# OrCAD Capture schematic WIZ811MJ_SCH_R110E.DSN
size B; title: WIZ811MJ; rev: 1.1; company: JaeHo Lee
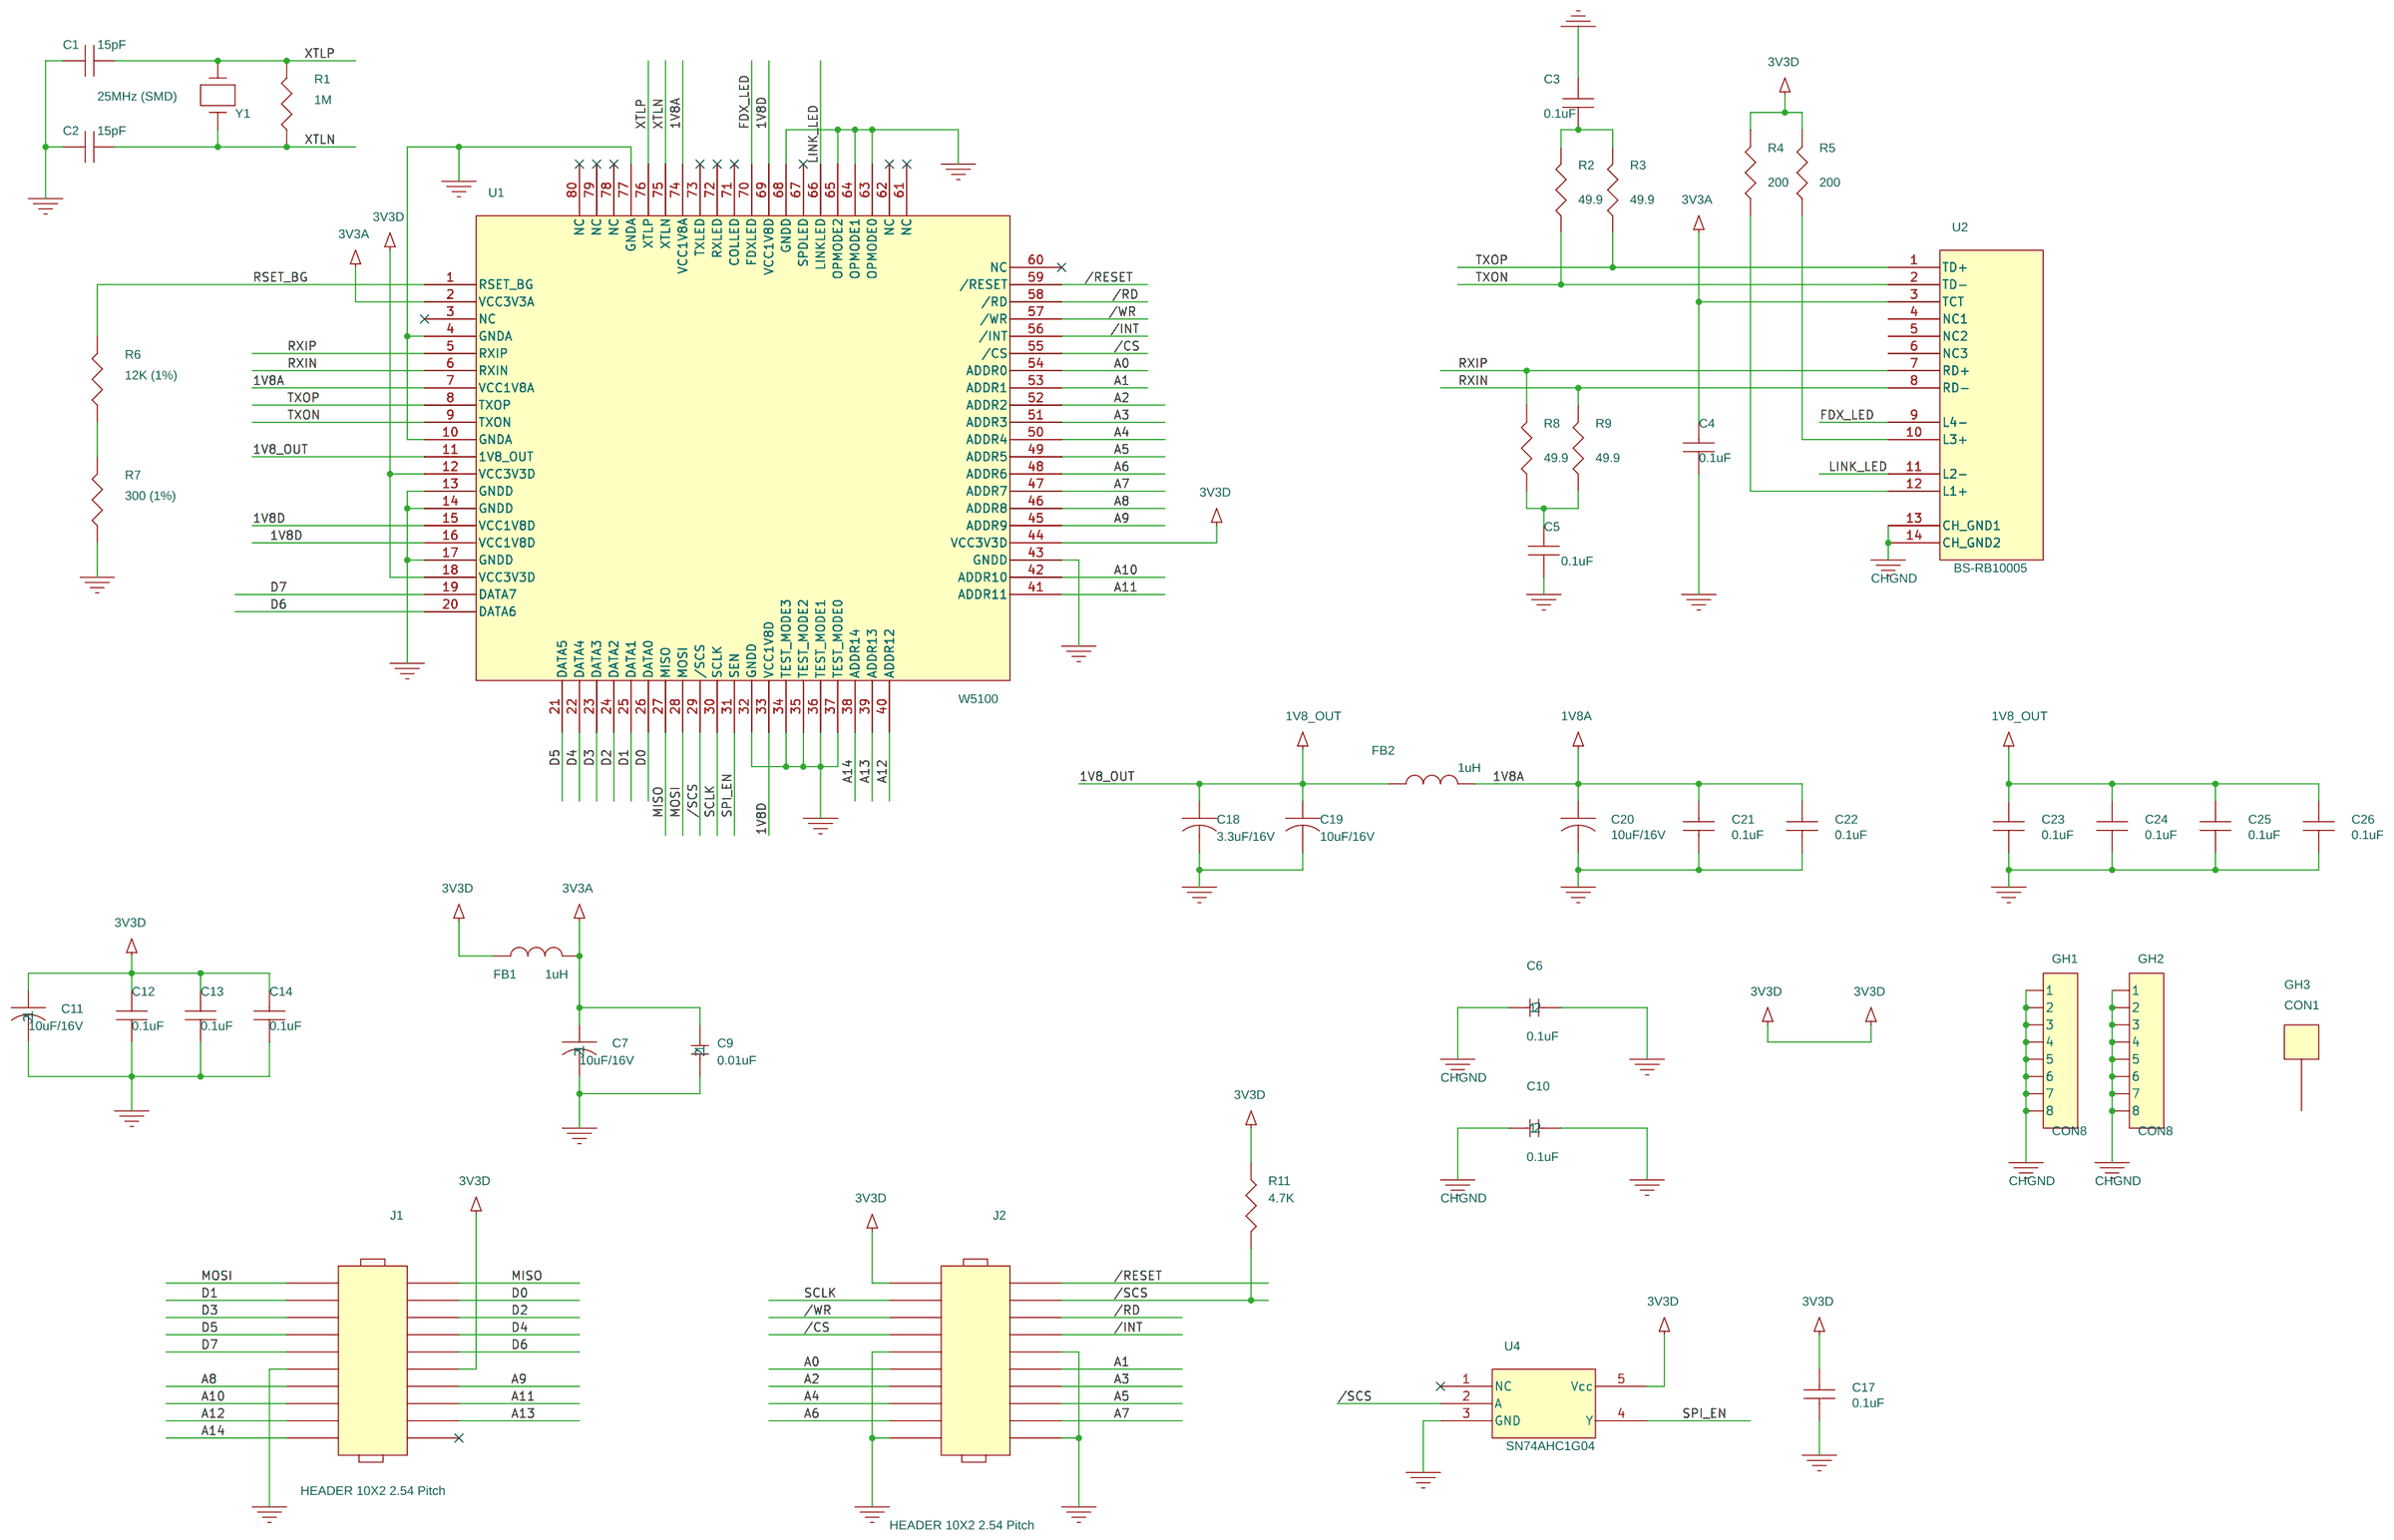
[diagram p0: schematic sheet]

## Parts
C1  15pF
C2  15pF
C3  0.1uF
C4  0.1uF
C5  0.1uF
C6  0.1uF  [C0603]
C7  10uF/16V  [CAP\B\3528]
C9  0.01uF  [C0603]
C10  0.1uF  [C0603]
C11  10uF/16V  [CAP\B\3528]
C12  0.1uF
C13  0.1uF
C14  0.1uF
C17  0.1uF
C18  3.3uF/16V
C19  10uF/16V
C20  10uF/16V
C21  0.1uF
C22  0.1uF
C23  0.1uF
C24  0.1uF
C25  0.1uF
C26  0.1uF
FB1  1uH  [L0805]
FB2  1uH  [L0805]
GH1  CON8
GH2  CON8
GH3  CON1
J1  HEADER 10X2 2.54 Pitch
J2  HEADER 10X2 2.54 Pitch
R1  1M
R2  49.9
R3  49.9
R4  200
R5  200
R6  12K (1%)
R7  300 (1%)
R8  49.9
R9  49.9
R11  4.7K
U1  W5100
U2  BS-RB10005
U4  SN74AHC1G04
Y1  25MHz (SMD)

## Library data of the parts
C1-C5 C12-C14 C17 C21-C26 = CAP_NP
C6 = CAP_0.01uF_0603
C7 = CAP_4.7uF_B
C9 = CAP_0.01uF_0603_2
C10 = CAP_0.01uF_0603_1
C11 = CAP_4.7uF_B_1
C18-C20 = C
FB1 FB2 = FB_0805
GH1 = CON8_1
GH2 = CON8
GH3 = CON1
J1 J2 = HEADER_10X2
R1-R9 R11 = R
U1 = W5100_7
U2 = RJ113BZ_0
U4 = SN74AHC1G04
Y1 = CRYSTAL

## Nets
1V8A: C20.1 C21.1 C22.1 FB2.2 U1.7(VCC1V8A) U1.74(VCC1V8A)
1V8D: C18.1 C19.1 C23.1 C24.1 C25.1 C26.1 FB2.1 U1.11(1V8_OUT) U1.15(VCC1V8D) U1.16(VCC1V8D) U1.33(VCC1V8D) U1.69(VCC1V8D)
3V3A: C4.1 C7.1 C9.1 FB1.2 U1.2(VCC3V3A) U2.3(TCT)
3V3D: C11.1 C12.1 C13.1 C14.1 C17.1 FB1.1 J1.12 J2.1 R4.2 R5.2 R11.1 U1.12(VCC3V3D) U1.18(VCC3V3D) U1.44(VCC3V3D) U4.5(Vcc)
GND: C1.2 C2.2 C3.1 C4.2 C5.2 C6.2 C7.2 C9.2 C10.2 C11.2 C12.2 C13.2 C14.2 C17.2 C18.2 C19.2 C20.2 C21.2 C22.2 C23.2 C24.2 C25.2 C26.2 J1.11 J2.9 J2.10 J2.19 J2.20 R7.1 U1.4(GNDA) U1.10(GNDA) U1.13(GNDD) U1.14(GNDD) U1.17(GNDD) U1.32(GNDD) U1.34(TEST_MODE3) U1.35(TEST_MODE2) U1.36(TEST_MODE1) U1.37(TEST_MODE0) U1.43(GNDD) U1.63(OPMODE0) U1.64(OPMODE1) U1.65(OPMODE2) U1.68(GNDD) U1.77(GNDA) U4.3(GND)
/CS: J2.7 U1.55(/CS)
/INT: J2.8 U1.56(/INT)
/RD: J2.6 U1.58(/RD)
/RESET: J2.2 U1.59(/RESET)
/SCS: J2.4 R11.2 U1.29(/SCS) U4.2(A)
/WR: J2.5 U1.57(/WR)
A0: J2.11 U1.54(ADDR0)
A1: J2.12 U1.53(ADDR1)
A2: J2.13 U1.52(ADDR2)
A3: J2.14 U1.51(ADDR3)
A4: J2.15 U1.50(ADDR4)
A5: J2.16 U1.49(ADDR5)
A6: J2.17 U1.48(ADDR6)
A7: J2.18 U1.47(ADDR7)
A8: J1.13 U1.46(ADDR8)
A9: J1.14 U1.45(ADDR9)
A10: J1.15 U1.42(ADDR10)
A11: J1.16 U1.41(ADDR11)
A12: J1.17 U1.40(ADDR12)
A13: J1.18 U1.39(ADDR13)
A14: J1.19 U1.38(ADDR14)
CHGND: C6.1 C10.1 GH1.1 GH1.2 GH1.3 GH1.4 GH1.5 GH1.6 GH1.7 GH1.8 GH2.1 GH2.2 GH2.3 GH2.4 GH2.5 GH2.6 GH2.7 GH2.8 U2.13(CH_GND1) U2.14(CH_GND2)
D0: J1.4 U1.26(DATA0)
D1: J1.3 U1.25(DATA1)
D2: J1.6 U1.24(DATA2)
D3: J1.5 U1.23(DATA3)
D4: J1.8 U1.22(DATA4)
D5: J1.7 U1.21(DATA5)
D6: J1.10 U1.20(DATA6)
D7: J1.9 U1.19(DATA7)
FDX_LED: U1.70(FDXLED) U2.9(L4-)
LINK_LED: U1.66(LINKLED) U2.11(L2-)
MISO: J1.2 U1.27(MISO)
MOSI: J1.1 U1.28(MOSI)
RSET_BG: R6.2 U1.1(RSET_BG)
RXIN: R9.2 U1.6(RXIN) U2.8(RD-)
RXIP: R8.2 U1.5(RXIP) U2.7(RD+)
SCLK: J2.3 U1.30(SCLK)
SPI_EN: U1.31(SEN) U4.4(Y)
TXON: R2.1 U1.9(TXON) U2.2(TD-)
TXOP: R3.1 U1.8(TXOP) U2.1(TD+)
XTLN: C2.1 R1.1 U1.75(XTLN) Y1.2
XTLP: C1.1 R1.2 U1.76(XTLP) Y1.1
N16777669: R6.1 R7.2
N16777748: R5.1 U2.10(L3+)
N16777792: R4.1 U2.12(L1+)
N16778076: C5.1 R8.1 R9.1
N16778090: C3.2 R2.2 R3.2

Not connected (* = marked no-connect by the designer): GH3 1; J1 20*; U1 3(NC)* 60(NC)* 61(NC)* 62(NC)* 67(SPDLED)* 71(COLLED)* 72(RXLED)* 73(TXLED)* 78(NC)* 79(NC)* 80(NC)*; U2 4(NC1) 5(NC2) 6(NC3); U4 1(NC)*
